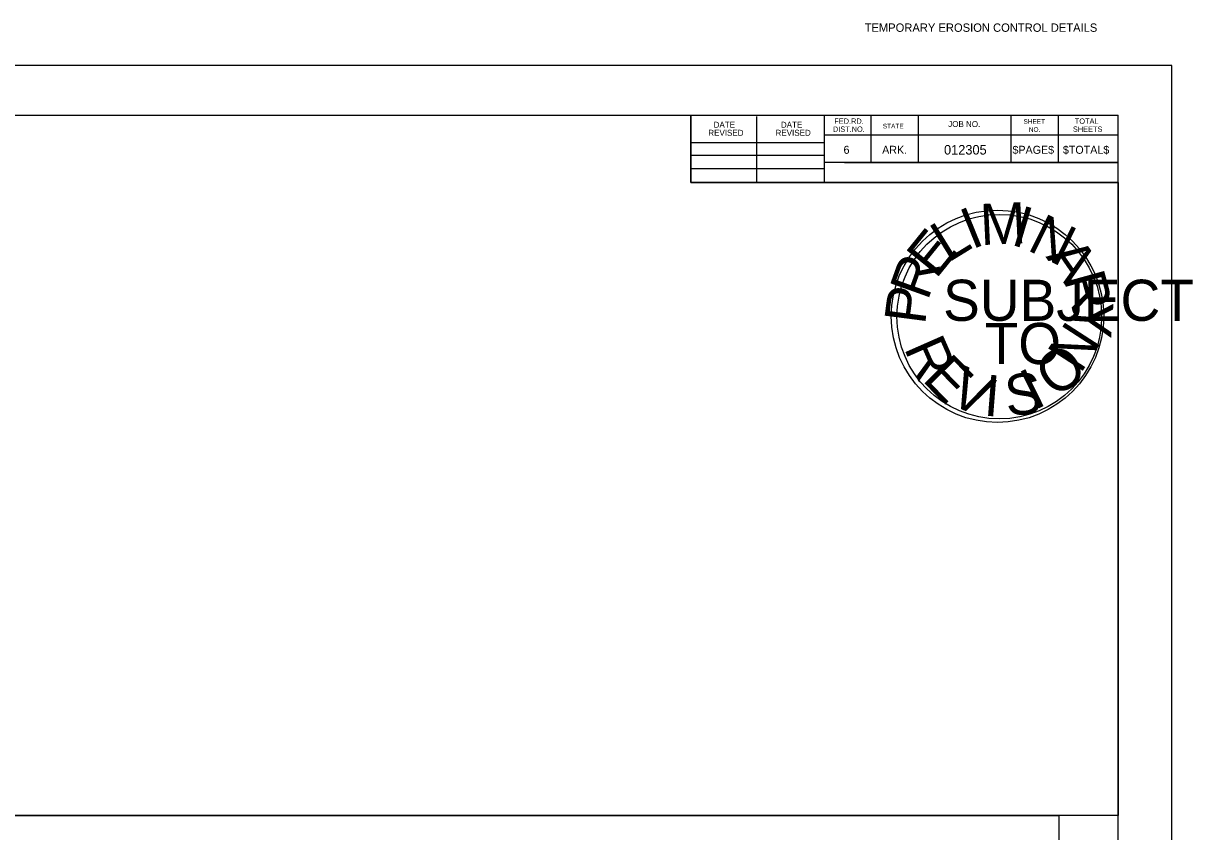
# Model space of a CAD drawing. Extents: x -1.6 to 32.7, y -1.7 to 21.9.
# Drawn here: x 15.57 to 32.71, y 10.04 to 21.89 of the extents above; entities that cross this region are included whole.
import ezdxf

# ---------------------------------------------------------------- set-up
doc = ezdxf.new("R2010")
doc.units = 0
for name, color, linetype in [('Level 1', 7, 'Continuous'), ('Level 4', 7, 'Continuous'), ('Level 62', 7, 'Continuous'), ('Level 63', 7, 'Continuous'), ('R_Border', 7, 'Continuous'), ('R_Border Prelim', 7, 'Continuous'), ('R_Border_Dark', 7, 'Continuous'), ('Stamp Mask', 7, 'Continuous'), ('TYPICAL FONT', 7, 'Continuous')]:
    doc.layers.add(name, color=color, linetype=linetype)

msp = doc.modelspace()

# ---------------------------------------------------------------- linework, layer by layer
at = {"layer": 'Level 1'}
for p, q in [((-0.001, 20.545), (31.617, 20.545)), ((25.353, 19.557), (25.353, 20.545)), ((26.321, 19.557), (26.321, 20.525)), ((27.307, 20.545), (27.307, 19.557)), ((27.991, 20.545), (27.991, 19.851)), ((28.685, 20.545), (28.685, 19.851)), ((30.043, 20.545), (30.043, 19.851)), ((30.737, 20.545), (30.737, 19.851)), ((31.617, -0.001), (31.617, 20.545)), ((31.617, 20.251), (27.307, 20.251)), ((31.617, 20.253), (31.617, 20.253)), ((25.353, 20.143), (27.307, 20.143)), ((25.353, 19.957), (27.307, 19.957)), ((25.353, 19.763), (27.307, 19.763)), ((31.617, 19.851), (27.307, 19.851)), ((27.603, 19.851), (31.617, 19.851)), ((31.617, 19.557), (25.353, 19.557))]:
    msp.add_line(p, q, dxfattribs=at)
for points in [[(-0.001, 20.545), (25.353, 20.545), (25.353, 19.557), (27.307, 19.557), (27.307, 19.557), (31.617, 19.557), (31.617, 10.272), (-0.001, 10.272)], [(0.745, 10.272), (30.745, 10.272), (30.745, 0.293), (0.745, 0.293)]]:
    msp.add_lwpolyline(points, close=True, dxfattribs=at)
at = {"layer": 'Level 4'}
msp.add_line((31.617, 10.272), (-0.001, 10.272), dxfattribs=at)
at = {"layer": 'Level 62'}
msp.add_lwpolyline([(-0.001, 20.545), (25.353, 20.545), (25.353, 20.545), (25.353, 19.557), (25.353, 19.557), (26.987, 19.557), (27.307, 19.557), (27.307, 19.557), (27.307, 19.557), (31.617, 19.557), (31.617, 10.272), (-0.001, 10.272)], close=True, dxfattribs=at)
at = {"layer": 'Level 63'}
msp.add_lwpolyline([(-1.598, -0.727), (32.402, -0.727), (32.402, 21.273), (-1.598, 21.273)], close=True, dxfattribs=at)
at = {"layer": 'R_Border Prelim'}
msp.add_circle((29.874, 17.589), 1.5, dxfattribs=at)
at = {"layer": 'R_Border_Dark'}
msp.add_line((31.617, 10.272), (-0.001, 10.272), dxfattribs=at)
at = {"layer": 'Stamp Mask'}
msp.add_circle((29.847, 17.594), 1.557, dxfattribs=at)

# ---------------------------------------------------------------- texts
at = {"layer": 'Level 1'}
for s, height, p in [('DATE', 0.0879, (25.687, 20.359)), ('DATE', 0.0879, (26.673, 20.359)), ('FED.RD.', 0.0782, (27.455, 20.417)), ('STATE', 0.0684, (28.167, 20.349)), ('SHEET', 0.0684, (30.229, 20.417)), ('TOTAL', 0.0782, (30.981, 20.417)), ('REVISED', 0.0879, (25.609, 20.241)), ('REVISED', 0.0879, (26.595, 20.241)), ('DIST.NO.', 0.0782, (27.435, 20.299)), ('NO.', 0.0684, (30.307, 20.299)), ('SHEETS', 0.0782, (30.953, 20.299)), ('6', 0.117, (27.591, 19.977)), ('ARK.', 0.1172, (28.157, 19.977)), ('012305', 0.14, (29.064, 19.966)), ('$PAGE$', 0.1172, (30.067, 19.977)), ('$TOTAL$', 0.1172, (30.806, 19.977))]:
    msp.add_text(s, height=height, dxfattribs=at).set_placement(p)
at = {"layer": 'R_Border'}
msp.add_text('JOB NO.', height=0.0879, dxfattribs=at).set_placement((29.125, 20.369))
msp.add_text('JOB NO.', height=0.0879, dxfattribs=at).set_placement((29.125, 20.369))
at = {"layer": 'R_Border Prelim'}
for s, rotation, p in [('M', 2.6943, (29.605, 18.637)), ('I', 343.3781, (30.027, 18.649)), ('I', 22.0105, (29.472, 18.571)), ('N', 333.7199, (30.266, 18.572)), ('E', 50.9849, (28.944, 18.13)), ('L', 31.6686, (29.122, 18.373)), ('A', 304.7456, (30.549, 18.468)), ('R', 70.3011, (28.824, 17.812)), ('R', 285.4294, (30.812, 18.162)), ('P', 82.6089, (28.784, 17.46)), ('Y', 266.1131, (30.947, 17.836)), ('N', 57.1378, (31.062, 16.738)), ('R', 293.7639, (28.471, 17.13)), ('E', 314.3262, (28.73, 16.659)), ('O', 36.5754, (30.697, 16.38)), ('V', 334.8885, (29.104, 16.332)), ('I', 26.2943, (30.389, 16.211)), ('I', 355.4508, (29.635, 16.139)), ('S', 5.732, (29.985, 16.128))]:
    msp.add_text(s, height=0.603, rotation=rotation, dxfattribs=at).set_placement(p)
for s, p in [('SUBJECT', (29.05, 17.527)), ('TO', (29.659, 16.893))]:
    msp.add_text(s, height=0.6034, dxfattribs=at).set_placement(p)
at = {"layer": 'TYPICAL FONT'}
msp.add_text('TEMPORARY EROSION CONTROL DETAILS', height=0.1224, dxfattribs=at).set_placement((27.9, 21.766))

doc.saveas('drawing.dxf')
